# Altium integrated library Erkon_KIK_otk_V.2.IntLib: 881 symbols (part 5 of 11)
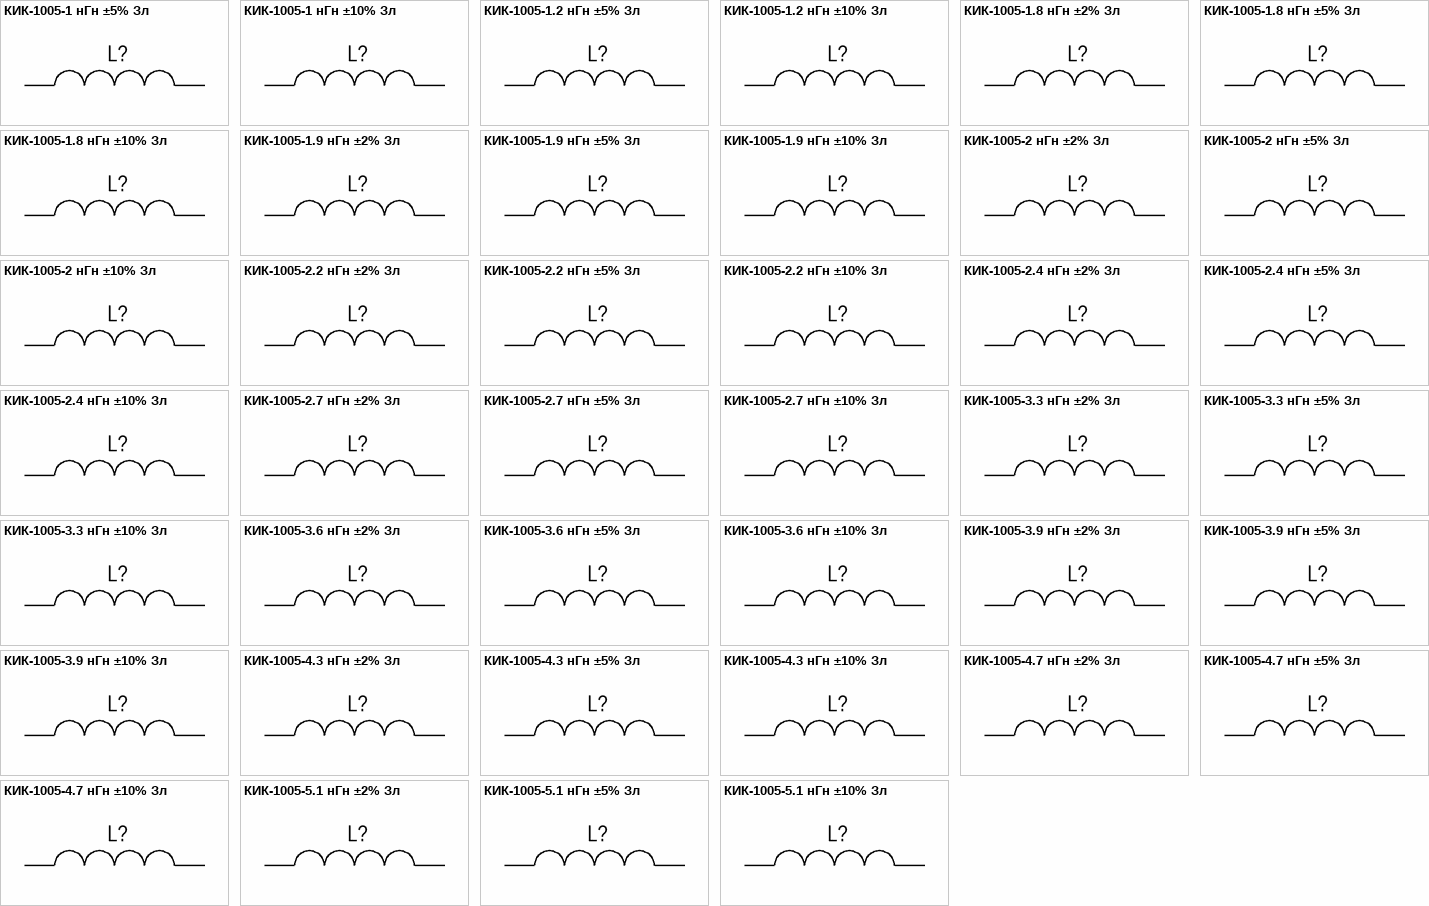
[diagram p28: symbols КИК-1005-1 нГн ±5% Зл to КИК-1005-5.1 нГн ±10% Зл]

## КИК-1005-1.9 нГн ±10% Зл
designator L?, comment 1.9 нГн ±10%  (value not drawn)
Катушка индуктивности с керамическим сердечником и золотым покрытием контактных площадок; Номиналиная индуктивность: 1.9 нГн; Добротность, не менее: 13; Резонансная частота, не менее: 11.30 ГГц; Сопротивление обмотки постоянноми току, не более: 0.090 Ом; Допустимый ток обмотки: 1040 мА; Изготовитель: АО "НПО "ЭРКОН"; Диапазон рабочих температур: от -60 до +125 ℃; Технология монтажа: SMT; Типоразмер: 1005 (0402); Упаковка: Катушка и лента
footprint КИК-1005_Зл (Катушка индуктивности с керамическим сердечником типоразмер 1005(0402))
pins: 1, 2

## КИК-1005-2 нГн ±2% Зл
designator L?, comment 2 нГн ±2%  (value not drawn)
Катушка индуктивности с керамическим сердечником и золотым покрытием контактных площадок; Номиналиная индуктивность: 2 нГн; Допускаемое отклонение индуктивности: ±5%; Добротность, не менее: 13; Резонансная частота, не менее: 11.10 ГГц; Сопротивление обмотки постоянноми току, не более: 0.090 Ом; Допустимый ток обмотки: 1040 мА; Диапазон рабочих температур: от -60 до +125 ℃; Изготовитель: АО "НПО "ЭРКОН"; Технология монтажа: SMT; Типоразмер: 1005 (0402); Упаковка: Катушка и лента
footprint КИК-1005_Зл (Катушка индуктивности с керамическим сердечником типоразмер 1005(0402))
pins: 1, 2

## КИК-1005-2 нГн ±5% Зл
designator L?, comment 2 нГн ±5%  (value not drawn)
Катушка индуктивности с керамическим сердечником и золотым покрытием контактных площадок; Номиналиная индуктивность: 2 нГн; Добротность, не менее: 13; Резонансная частота, не менее: 11.10 ГГц; Сопротивление обмотки постоянноми току, не более: 0.090 Ом; Допустимый ток обмотки: 1040 мА; Диапазон рабочих температур: от -60 до +125 ℃; Изготовитель: АО "НПО "ЭРКОН"; Технология монтажа: SMT; Типоразмер: 1005 (0402); Упаковка: Катушка и лента
footprint КИК-1005_Зл (Катушка индуктивности с керамическим сердечником типоразмер 1005(0402))
pins: 1, 2

## КИК-1005-2 нГн ±10% Зл
designator L?, comment 2 нГн ±10%  (value not drawn)
Катушка индуктивности с керамическим сердечником и золотым покрытием контактных площадок; Номиналиная индуктивность: 2 нГн; Добротность, не менее: 13; Резонансная частота, не менее: 11.10 ГГц; Сопротивление обмотки постоянноми току, не более: 0.090 Ом; Допустимый ток обмотки: 1040 мА; Изготовитель: АО "НПО "ЭРКОН"; Диапазон рабочих температур: от -60 до +125 ℃; Технология монтажа: SMT; Типоразмер: 1005 (0402); Упаковка: Катушка и лента
footprint КИК-1005_Зл (Катушка индуктивности с керамическим сердечником типоразмер 1005(0402))
pins: 1, 2

## КИК-1005-2.2 нГн ±2% Зл
designator L?, comment 2.2 нГн ±2%  (value not drawn)
Катушка индуктивности с керамическим сердечником и золотым покрытием контактных площадок; Номиналиная индуктивность: 2.2 нГн; Добротность, не менее: 18; Резонансная частота, не менее: 10.80 ГГц; Сопротивление обмотки постоянноми току, не более: 0.090 Ом; Допустимый ток обмотки: 960 мА; Изготовитель: АО "НПО "ЭРКОН"; Диапазон рабочих температур: от -60 до +125 ℃; Технология монтажа: SMT; Типоразмер: 1005 (0402); Упаковка: Катушка и лента
footprint КИК-1005_Зл (Катушка индуктивности с керамическим сердечником типоразмер 1005(0402))
pins: 1, 2

## КИК-1005-2.2 нГн ±5% Зл
designator L?, comment 2.2 нГн ±5%  (value not drawn)
Катушка индуктивности с керамическим сердечником и золотым покрытием контактных площадок; Номиналиная индуктивность: 2.2 нГн; Добротность, не менее: 18; Резонансная частота, не менее: 10.80 ГГц; Сопротивление обмотки постоянноми току, не более: 0.090 Ом; Допустимый ток обмотки: 960 мА; Изготовитель: АО "НПО "ЭРКОН"; Диапазон рабочих температур: от -60 до +125 ℃; Технология монтажа: SMT; Типоразмер: 1005 (0402); Упаковка: Катушка и лента
footprint КИК-1005_Зл (Катушка индуктивности с керамическим сердечником типоразмер 1005(0402))
pins: 1, 2

## КИК-1005-2.2 нГн ±10% Зл
designator L?, comment 2.2 нГн ±10%  (value not drawn)
Катушка индуктивности с керамическим сердечником и золотым покрытием контактных площадок; Номиналиная индуктивность: 2.2 нГн; Добротность, не менее: 18; Резонансная частота, не менее: 10.80 ГГц; Сопротивление обмотки постоянноми току, не более: 0.090 Ом; Допустимый ток обмотки: 960 мА; Диапазон рабочих температур: от -60 до +125 ℃; Технология монтажа: SMT; Типоразмер: 1005 (0402); Упаковка: Катушка и лента
footprint КИК-1005_Зл (Катушка индуктивности с керамическим сердечником типоразмер 1005(0402))
pins: 1, 2

## КИК-1005-2.4 нГн ±2% Зл
designator L?, comment 2.4нГн ±2%  (value not drawn)
Катушка индуктивности с керамическим сердечником и золотым покрытием контактных площадок; Добротность, не менее: 18; Резонансная частота, не менее: 10.50 ГГц; Сопротивление обмотки постоянноми току, не более: 0.090 Ом; Допустимый ток обмотки: 790 мА; Изготовитель: АО "НПО "ЭРКОН"; Диапазон рабочих температур: от -60 до +125 ℃; Технология монтажа: SMT; Типоразмер: 1005 (0402); Упаковка: Катушка и лента
footprint КИК-1005_Зл (Катушка индуктивности с керамическим сердечником типоразмер 1005(0402))
pins: 1, 2

## КИК-1005-2.4 нГн ±5% Зл
designator L?, comment 2.4нГн ±5%  (value not drawn)
Катушка индуктивности с керамическим сердечником и золотым покрытием контактных площадок; Добротность, не менее: 18; Резонансная частота, не менее: 10.50 ГГц; Сопротивление обмотки постоянноми току, не более: 0.090 Ом; Допустимый ток обмотки: 790 мА; Изготовитель: АО "НПО "ЭРКОН"; Диапазон рабочих температур: от -60 до +125 ℃; Технология монтажа: SMT; Типоразмер: 1005 (0402); Упаковка: Катушка и лента
footprint КИК-1005_Зл (Катушка индуктивности с керамическим сердечником типоразмер 1005(0402))
pins: 1, 2

## КИК-1005-2.4 нГн ±10% Зл
designator L?, comment 2.4нГн ±10%  (value not drawn)
Катушка индуктивности с керамическим сердечником и золотым покрытием контактных площадок; Добротность, не менее: 18; Резонансная частота, не менее: 10.50 ГГц; Сопротивление обмотки постоянноми току, не более: 0.090 Ом; Допустимый ток обмотки: 790 мА; Изготовитель: АО "НПО "ЭРКОН"; Диапазон рабочих температур: от -60 до +125 ℃; Технология монтажа: SMT; Типоразмер: 1005 (0402); Упаковка: Катушка и лента
footprint КИК-1005_Зл (Катушка индуктивности с керамическим сердечником типоразмер 1005(0402))
pins: 1, 2

## КИК-1005-2.7 нГн ±2% Зл
designator L?, comment 2.7 нГн ±2%  (value not drawn)
Катушка индуктивности с керамическим сердечником и золотым покрытием контактных площадок; Номиналиная индуктивность: 2.4 нГн; Добротность, не менее: 18; Резонансная частота, не менее: 10.40 ГГц; Сопротивление обмотки постоянноми току, не более: 0.120 Ом; Допустимый ток обмотки: 640 мА; Изготовитель: АО "НПО "ЭРКОН"; Диапазон рабочих температур: от -60 до +125 ℃; Технология монтажа: SMT; Типоразмер: 1005 (0402); Упаковка: Катушка и лента
footprint КИК-1005_Зл (Катушка индуктивности с керамическим сердечником типоразмер 1005(0402))
pins: 1, 2

## КИК-1005-2.7 нГн ±5% Зл
designator L?, comment 2.7 нГн ±5%  (value not drawn)
Катушка индуктивности с керамическим сердечником и золотым покрытием контактных площадок; Номиналиная индуктивность: 2.4 нГн; Добротность, не менее: 18; Резонансная частота, не менее: 10.40 ГГц; Сопротивление обмотки постоянноми току, не более: 0.120 Ом; Допустимый ток обмотки: 640 мА; Изготовитель: АО "НПО "ЭРКОН"; Диапазон рабочих температур: от -60 до +125 ℃; Технология монтажа: SMT; Типоразмер: 1005 (0402); Упаковка: Катушка и лента
footprint КИК-1005_Зл (Катушка индуктивности с керамическим сердечником типоразмер 1005(0402))
pins: 1, 2

## КИК-1005-2.7 нГн ±10% Зл
designator L?, comment 2.7 нГн ±10%  (value not drawn)
Катушка индуктивности с керамическим сердечником и золотым покрытием контактных площадок; Номиналиная индуктивность: 2.4 нГн; Добротность, не менее: 18; Резонансная частота, не менее: 10.40 ГГц; Сопротивление обмотки постоянноми току, не более: 0.120 Ом; Допустимый ток обмотки: 640 мА; Изготовитель: АО "НПО "ЭРКОН"; Диапазон рабочих температур: от -60 до +125 ℃; Технология монтажа: SMT; Типоразмер: 1005 (0402); Упаковка: Катушка и лента
footprint КИК-1005_Зл (Катушка индуктивности с керамическим сердечником типоразмер 1005(0402))
pins: 1, 2

## КИК-1005-3.3 нГн ±2% Зл
designator L?, comment 3.3 нГн ±2%  (value not drawn)
Катушка индуктивности с керамическим сердечником и золотым покрытием контактных площадок; Номиналиная индуктивность: 3.3нГн; Добротность, не менее: 20; Резонансная частота, не менее: 7.00 ГГц; Сопротивление обмотки постоянноми току, не более: 0.066 Ом; Допустимый ток обмотки: 840 мА; Изготовитель: АО "НПО "ЭРКОН"; Диапазон рабочих температур: от -60 до +125 ℃; Технология монтажа: SMT; Типоразмер: 1005 (0402); Упаковка: Катушка и лента
footprint КИК-1005_Зл (Катушка индуктивности с керамическим сердечником типоразмер 1005(0402))
pins: 1, 2

## КИК-1005-3.3 нГн ±5% Зл
designator L?, comment 3.3 нГн ±5%  (value not drawn)
Катушка индуктивности с керамическим сердечником и золотым покрытием контактных площадок; Номиналиная индуктивность: 3.3нГн; Добротность, не менее: 20; Резонансная частота, не менее: 7.00 ГГц; Сопротивление обмотки постоянноми току, не более: 0.066 Ом; Допустимый ток обмотки: 840 мА; Изготовитель: АО "НПО "ЭРКОН"; Диапазон рабочих температур: от -60 до +125 ℃; Технология монтажа: SMT; Типоразмер: 1005 (0402); Упаковка: Катушка и лента
footprint КИК-1005_Зл (Катушка индуктивности с керамическим сердечником типоразмер 1005(0402))
pins: 1, 2

## КИК-1005-3.3 нГн ±10% Зл
designator L?, comment 3.3 нГн ±10%  (value not drawn)
Катушка индуктивности с керамическим сердечником и золотым покрытием контактных площадок; Номиналиная индуктивность: 3.3нГн; Добротность, не менее: 20; Резонансная частота, не менее: 7.00 ГГц; Сопротивление обмотки постоянноми току, не более: 0.066 Ом; Допустимый ток обмотки: 840 мА; Изготовитель: АО "НПО "ЭРКОН"; Диапазон рабочих температур: от -60 до +125 ℃; Технология монтажа: SMT; Типоразмер: 1005 (0402); Упаковка: Катушка и лента
footprint КИК-1005_Зл (Катушка индуктивности с керамическим сердечником типоразмер 1005(0402))
pins: 1, 2

## КИК-1005-3.6 нГн ±2% Зл
designator L?, comment 3.6 нГн ±2%  (value not drawn)
Катушка индуктивности с керамическим сердечником и золотым покрытием контактных площадок; Номиналиная индуктивность: 3.6нГн; Добротность, не менее: 20; Резонансная частота, не менее: 6.80 ГГц; Сопротивление обмотки постоянноми току, не более: 0.066 Ом; Допустимый ток обмотки: 840 мА; Изготовитель: АО "НПО "ЭРКОН"; Диапазон рабочих температур: от -60 до +125 ℃; Технология монтажа: SMT; Типоразмер: 1005 (0402); Упаковка: Катушка и лента
footprint КИК-1005_Зл (Катушка индуктивности с керамическим сердечником типоразмер 1005(0402))
pins: 1, 2

## КИК-1005-3.6 нГн ±5% Зл
designator L?, comment 3.6 нГн ±5%  (value not drawn)
Катушка индуктивности с керамическим сердечником и золотым покрытием контактных площадок; Номиналиная индуктивность: 3.6нГн; Добротность, не менее: 20; Резонансная частота, не менее: 6.80 ГГц; Сопротивление обмотки постоянноми току, не более: 0.066 Ом; Допустимый ток обмотки: 840 мА; Изготовитель: АО "НПО "ЭРКОН"; Диапазон рабочих температур: от -60 до +125 ℃; Технология монтажа: SMT; Типоразмер: 1005 (0402); Упаковка: Катушка и лента
footprint КИК-1005_Зл (Катушка индуктивности с керамическим сердечником типоразмер 1005(0402))
pins: 1, 2

## КИК-1005-3.6 нГн ±10% Зл
designator L?, comment 3.6 нГн ±10%  (value not drawn)
Катушка индуктивности с керамическим сердечником и золотым покрытием контактных площадок; Номиналиная индуктивность: 3.6нГн; Допускаемое отклонение индуктивности: ±5%; Добротность, не менее: 20; Резонансная частота, не менее: 6.80 ГГц; Сопротивление обмотки постоянноми току, не более: 0.066 Ом; Допустимый ток обмотки: 840 мА; Изготовитель: АО "НПО "ЭРКОН"; Диапазон рабочих температур: от -60 до +125 ℃; Технология монтажа: SMT; Типоразмер: 1005 (0402); Упаковка: Катушка и лента
footprint КИК-1005_Зл (Катушка индуктивности с керамическим сердечником типоразмер 1005(0402))
pins: 1, 2

## КИК-1005-3.9 нГн ±2% Зл
designator L?, comment 3.9 нГн ±2%  (value not drawn)
Катушка индуктивности с керамическим сердечником и золотым покрытием контактных площадок; Номиналиная индуктивность: 3.9нГн; Добротность, не менее: 20; Резонансная частота, не менее: 6.00 ГГц; Сопротивление обмотки постоянноми току, не более: 0.066 Ом; Допустимый ток обмотки: 840 мА; Изготовитель: АО "НПО "ЭРКОН"; Диапазон рабочих температур: от -60 до +125 ℃; Технология монтажа: SMT; Типоразмер: 1005 (0402); Упаковка: Катушка и лента
footprint КИК-1005_Зл (Катушка индуктивности с керамическим сердечником типоразмер 1005(0402))
pins: 1, 2

## КИК-1005-3.9 нГн ±5% Зл
designator L?, comment 3.9 нГн ±5%  (value not drawn)
Катушка индуктивности с керамическим сердечником и золотым покрытием контактных площадок; Номиналиная индуктивность: 3.9нГн; Добротность, не менее: 20; Резонансная частота, не менее: 6.00 ГГц; Сопротивление обмотки постоянноми току, не более: 0.066 Ом; Допустимый ток обмотки: 840 мА; Изготовитель: АО "НПО "ЭРКОН"; Диапазон рабочих температур: от -60 до +125 ℃; Технология монтажа: SMT; Типоразмер: 1005 (0402); Упаковка: Катушка и лента
footprint КИК-1005_Зл (Катушка индуктивности с керамическим сердечником типоразмер 1005(0402))
pins: 1, 2

## КИК-1005-3.9 нГн ±10% Зл
designator L?, comment 3.9 нГн ±10%  (value not drawn)
Катушка индуктивности с керамическим сердечником и золотым покрытием контактных площадок; Номиналиная индуктивность: 3.9нГн; Добротность, не менее: 20; Резонансная частота, не менее: 6.00 ГГц; Сопротивление обмотки постоянноми току, не более: 0.066 Ом; Допустимый ток обмотки: 840 мА; Изготовитель: АО "НПО "ЭРКОН"; Диапазон рабочих температур: от -60 до +125 ℃; Технология монтажа: SMT; Типоразмер: 1005 (0402); Упаковка: Катушка и лента
footprint КИК-1005_Зл (Катушка индуктивности с керамическим сердечником типоразмер 1005(0402))
pins: 1, 2

## КИК-1005-4.3 нГн ±2% Зл
designator L?, comment 4.3 нГн ±2%  (value not drawn)
Катушка индуктивности с керамическим сердечником и золотым покрытием контактных площадок; Номиналиная индуктивность: 4.3 нГн; Добротность, не менее: 20; Резонансная частота, не менее: 6.00 ГГц; Сопротивление обмотки постоянноми току, не более: 0.091 Ом; Допустимый ток обмотки: 700 мА; Изготовитель: АО "НПО "ЭРКОН"; Диапазон рабочих температур: SMT; Типоразмер: 1005 (0402); Упаковка: Катушка и лента
footprint КИК-1005_Зл (Катушка индуктивности с керамическим сердечником типоразмер 1005(0402))
pins: 1, 2

## КИК-1005-4.3 нГн ±5% Зл
designator L?, comment 4.3 нГн ±5%  (value not drawn)
Катушка индуктивности с керамическим сердечником и золотым покрытием контактных площадок; Номиналиная индуктивность: 4.3 нГн; Добротность, не менее: 20; Резонансная частота, не менее: 6.00 ГГц; Сопротивление обмотки постоянноми току, не более: 0.091 Ом; Допустимый ток обмотки: 700 мА; Изготовитель: АО "НПО "ЭРКОН"; Диапазон рабочих температур: SMT; Типоразмер: 1005 (0402); Упаковка: Катушка и лента
footprint КИК-1005_Зл (Катушка индуктивности с керамическим сердечником типоразмер 1005(0402))
pins: 1, 2

## КИК-1005-4.3 нГн ±10% Зл
designator L?, comment 4.3 нГн ±10%  (value not drawn)
Катушка индуктивности с керамическим сердечником и золотым покрытием контактных площадок; Номиналиная индуктивность: 4.3нГн; Добротность, не менее: 20; Резонансная частота, не менее: 6.00 ГГц; Сопротивление обмотки постоянноми току, не более: 0.091 Ом; Допустимый ток обмотки: 700 мА; Изготовитель: АО "НПО "ЭРКОН"; Диапазон рабочих температур: от -60 до +125 ℃; Технология монтажа: SMT; Типоразмер: 1005 (0402); Упаковка: Катушка и лента
footprint КИК-1005_Зл (Катушка индуктивности с керамическим сердечником типоразмер 1005(0402))
pins: 1, 2

## КИК-1005-4.7 нГн ±2% Зл
designator L?, comment 4.7 нГн ±2%  (value not drawn)
Катушка индуктивности с керамическим сердечником и золотым покрытием контактных площадок; Номиналиная индуктивность: 4.7 нГн; Добротность, не менее: 18; Резонансная частота, не менее: 4.77 ГГц; Сопротивление обмотки постоянноми току, не более: 0.130 Ом; Допустимый ток обмотки: 640 мА; Изготовитель: АО "НПО "ЭРКОН"; Диапазон рабочих температур: от -60 до +125 ℃; Технология монтажа: SMT; Типоразмер: 1005 (0402); Упаковка: Катушка и лента
footprint КИК-1005_Зл (Катушка индуктивности с керамическим сердечником типоразмер 1005(0402))
pins: 1, 2

## КИК-1005-4.7 нГн ±5% Зл
designator L?, comment 4.7 нГн ±5%  (value not drawn)
Катушка индуктивности с керамическим сердечником и золотым покрытием контактных площадок; Номиналиная индуктивность: 4.7 нГн; Добротность, не менее: 18; Резонансная частота, не менее: 4.77 ГГц; Сопротивление обмотки постоянноми току, не более: 0.130 Ом; Допустимый ток обмотки: 640 мА; Изготовитель: АО "НПО "ЭРКОН"; Диапазон рабочих температур: от -60 до +125 ℃; Технология монтажа: SMT; Типоразмер: 1005 (0402); Упаковка: Катушка и лента
footprint КИК-1005_Зл (Катушка индуктивности с керамическим сердечником типоразмер 1005(0402))
pins: 1, 2

## КИК-1005-4.7 нГн ±10% Зл
designator L?, comment 4.7 нГн ±10%  (value not drawn)
Катушка индуктивности с керамическим сердечником и золотым покрытием контактных площадок; Номиналиная индуктивность: 4.7 нГн; Добротность, не менее: 18; Резонансная частота, не менее: 4.77 ГГц; Сопротивление обмотки постоянноми току, не более: 0.130 Ом; Допустимый ток обмотки: 640 мА; Изготовитель: АО "НПО "ЭРКОН"; Диапазон рабочих температур: от -60 до +125 ℃; Технология монтажа: SMT; Типоразмер: 1005 (0402); Упаковка: Катушка и лента
footprint КИК-1005_Зл (Катушка индуктивности с керамическим сердечником типоразмер 1005(0402))
pins: 1, 2

## КИК-1005-5.1 нГн ±2% Зл
designator L?, comment 5.1нГн ±2%  (value not drawn)
Катушка индуктивности с керамическим сердечником и золотым покрытием контактных площадок; Добротность, не менее: 20; Резонансная частота, не менее: 4.80 ГГц; Сопротивление обмотки постоянноми току, не более: 0.083 Ом; Допустимый ток обмотки: 800 мА; Изготовитель: АО "НПО "ЭРКОН"; Диапазон рабочих температур: от -60 до +125 ℃; Технология монтажа: SMT; Типоразмер: 1005 (0402); Упаковка: Катушка и лента
footprint КИК-1005_Зл (Катушка индуктивности с керамическим сердечником типоразмер 1005(0402))
pins: 1, 2

## КИК-1005-5.1 нГн ±5% Зл
designator L?, comment 5.1нГн ±5%  (value not drawn)
Катушка индуктивности с керамическим сердечником и золотым покрытием контактных площадок; Добротность, не менее: 20; Резонансная частота, не менее: 4.80 ГГц; Сопротивление обмотки постоянноми току, не более: 0.083 Ом; Допустимый ток обмотки: 800 мА; Изготовитель: АО "НПО "ЭРКОН"; Диапазон рабочих температур: от -60 до +125 ℃; Технология монтажа: SMT; Типоразмер: 1005 (0402); Упаковка: Катушка и лента
footprint КИК-1005_Зл (Катушка индуктивности с керамическим сердечником типоразмер 1005(0402))
pins: 1, 2

## КИК-1005-5.1 нГн ±10% Зл
designator L?, comment 5.1нГн ±10%  (value not drawn)
Катушка индуктивности с керамическим сердечником и золотым покрытием контактных площадок; Добротность, не менее: 20; Резонансная частота, не менее: 4.80 ГГц; Сопротивление обмотки постоянноми току, не более: 0.083 Ом; Допустимый ток обмотки: 800 мА; Изготовитель: АО "НПО "ЭРКОН"; Диапазон рабочих температур: от -60 до +125 ℃; Технология монтажа: SMT; Типоразмер: 1005 (0402); Упаковка: Катушка и лента
footprint КИК-1005_Зл (Катушка индуктивности с керамическим сердечником типоразмер 1005(0402))
pins: 1, 2

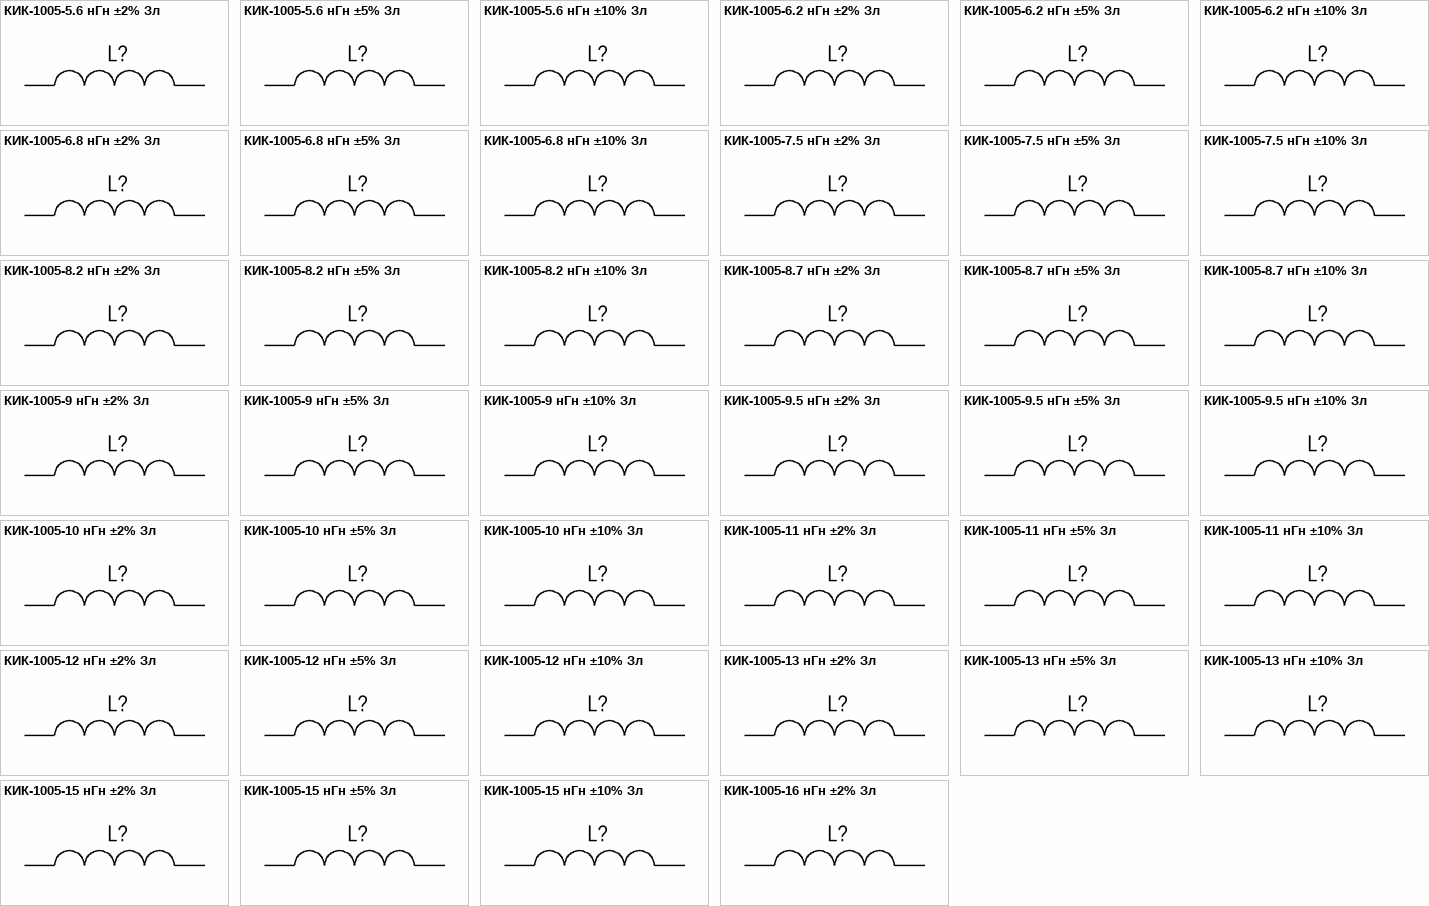
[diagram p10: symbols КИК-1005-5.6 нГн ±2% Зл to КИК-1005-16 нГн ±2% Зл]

## КИК-1005-5.6 нГн ±2% Зл
designator L?, comment 5.6нГн ±2%  (value not drawn)
Катушка индуктивности с керамическим сердечником и золотым покрытием контактных площадок; Добротность, не менее: 20; Резонансная частота, не менее: 4.80 ГГц; Сопротивление обмотки постоянноми току, не более: 0.083 Ом; Допустимый ток обмотки: 760 мА; Изготовитель: АО "НПО "ЭРКОН"; Диапазон рабочих температур: от -60 до +125 ℃; Технология монтажа: SMT; Типоразмер: 1005 (0402); Упаковка: Катушка и лента
footprint КИК-1005_Зл (Катушка индуктивности с керамическим сердечником типоразмер 1005(0402))
pins: 1, 2

## КИК-1005-5.6 нГн ±5% Зл
designator L?, comment 5.6нГн ±5%  (value not drawn)
Катушка индуктивности с керамическим сердечником и золотым покрытием контактных площадок; Добротность, не менее: 20; Резонансная частота, не менее: 4.80 ГГц; Сопротивление обмотки постоянноми току, не более: 0.083 Ом; Допустимый ток обмотки: 760 мА; Изготовитель: АО "НПО "ЭРКОН"; Диапазон рабочих температур: от -60 до +125 ℃; Технология монтажа: SMT; Типоразмер: 1005 (0402); Упаковка: Катушка и лента
footprint КИК-1005_Зл (Катушка индуктивности с керамическим сердечником типоразмер 1005(0402))
pins: 1, 2

## КИК-1005-5.6 нГн ±10% Зл
designator L?, comment 5.6 нГн ±10%  (value not drawn)
Катушка индуктивности с керамическим сердечником и золотым покрытием контактных площадок; Номиналиная индуктивность: 5.6нГн; Добротность, не менее: 20; Резонансная частота, не менее: 4.80 ГГц; Сопротивление обмотки постоянноми току, не более: 0.083 Ом; Допустимый ток обмотки: 760 мА; Изготовитель: АО "НПО "ЭРКОН"; Диапазон рабочих температур: от -60 до +125 ℃; Технология монтажа: SMT; Типоразмер: 1005 (0402); Упаковка: Катушка и лента
footprint КИК-1005_Зл (Катушка индуктивности с керамическим сердечником типоразмер 1005(0402))
pins: 1, 2

## КИК-1005-6.2 нГн ±2% Зл
designator L?, comment 6.2 нГн ±2%  (value not drawn)
Катушка индуктивности с керамическим сердечником и золотым покрытием контактных площадок; Номиналиная индуктивность: 5.6нГн; Допускаемое отклонение индуктивности: ±5%; Добротность, не менее: 20; Резонансная частота, не менее: 4.80 ГГц; Сопротивление обмотки постоянноми току, не более: 0.083 Ом; Допустимый ток обмотки: 760 мА; Изготовитель: АО "НПО "ЭРКОН"; Диапазон рабочих температур: от -60 до +125 ℃; Технология монтажа: SMT; Типоразмер: 1005 (0402); Упаковка: Катушка и лента
footprint КИК-1005_Зл (Катушка индуктивности с керамическим сердечником типоразмер 1005(0402))
pins: 1, 2

## КИК-1005-6.2 нГн ±5% Зл
designator L?, comment 6.2 нГн ±5%  (value not drawn)
Катушка индуктивности с керамическим сердечником и золотым покрытием контактных площадок; Номиналиная индуктивность: 5.6нГн; Добротность, не менее: 20; Резонансная частота, не менее: 4.80 ГГц; Сопротивление обмотки постоянноми току, не более: 0.083 Ом; Допустимый ток обмотки: 760 мА; Изготовитель: АО "НПО "ЭРКОН"; Диапазон рабочих температур: от -60 до +125 ℃; Технология монтажа: SMT; Типоразмер: 1005 (0402); Упаковка: Катушка и лента
footprint КИК-1005_Зл (Катушка индуктивности с керамическим сердечником типоразмер 1005(0402))
pins: 1, 2

## КИК-1005-6.2 нГн ±10% Зл
designator L?, comment 6.2 нГн ±10%  (value not drawn)
Катушка индуктивности с керамическим сердечником и золотым покрытием контактных площадок; Номиналиная индуктивность: 5.6нГн; Добротность, не менее: 20; Резонансная частота, не менее: 4.80 ГГц; Сопротивление обмотки постоянноми току, не более: 0.083 Ом; Допустимый ток обмотки: 760 мА; Изготовитель: АО "НПО "ЭРКОН"; Диапазон рабочих температур: от -60 до +125 ℃; Технология монтажа: SMT; Типоразмер: 1005 (0402); Упаковка: Катушка и лента
footprint КИК-1005_Зл (Катушка индуктивности с керамическим сердечником типоразмер 1005(0402))
pins: 1, 2

## КИК-1005-6.8 нГн ±2% Зл
designator L?, comment 6.8 нГн ±2%  (value not drawn)
Катушка индуктивности с керамическим сердечником и золотым покрытием контактных площадок; Номиналиная индуктивность: 5.6нГн; Допускаемое отклонение индуктивности: ±5%; Добротность, не менее: 20; Резонансная частота, не менее: 4.80 ГГц; Сопротивление обмотки постоянноми току, не более: 0.083 Ом; Допустимый ток обмотки: 680 мА; Изготовитель: АО "НПО "ЭРКОН"; Диапазон рабочих температур: от -60 до +125 ℃; Технология монтажа: SMT; Типоразмер: 1005 (0402); Упаковка: Катушка и лента
footprint КИК-1005_Зл (Катушка индуктивности с керамическим сердечником типоразмер 1005(0402))
pins: 1, 2

## КИК-1005-6.8 нГн ±5% Зл
designator L?, comment 6.8 нГн ±5%  (value not drawn)
Катушка индуктивности с керамическим сердечником и золотым покрытием контактных площадок; Номиналиная индуктивность: 5.6нГн; Добротность, не менее: 20; Резонансная частота, не менее: 4.80 ГГц; Сопротивление обмотки постоянноми току, не более: 0.083 Ом; Допустимый ток обмотки: 680 мА; Изготовитель: АО "НПО "ЭРКОН"; Диапазон рабочих температур: от -60 до +125 ℃; Технология монтажа: SMT; Типоразмер: 1005 (0402); Упаковка: Катушка и лента
footprint КИК-1005_Зл (Катушка индуктивности с керамическим сердечником типоразмер 1005(0402))
pins: 1, 2

## КИК-1005-6.8 нГн ±10% Зл
designator L?, comment 10 нГн ±5%  (value not drawn)
Катушка индуктивности с керамическим сердечником и золотым покрытием контактных площадок; Номиналиная индуктивность: 5.6нГн; Допускаемое отклонение индуктивности: ±10%; Добротность, не менее: 20; Резонансная частота, не менее: 4.80 ГГц; Сопротивление обмотки постоянноми току, не более: 0.083 Ом; Допустимый ток обмотки: 680 мА; Изготовитель: АО "НПО "ЭРКОН"; Диапазон рабочих температур: от -60 до +125 ℃; Технология монтажа: SMT; Типоразмер: 1005 (0402); Упаковка: Катушка и лента
footprint КИК-1005_Зл (Катушка индуктивности с керамическим сердечником типоразмер 1005(0402))
pins: 1, 2

## КИК-1005-7.5 нГн ±2% Зл
designator L?, comment 7.5 нГн ±2%  (value not drawn)
Катушка индуктивности с керамическим сердечником и золотым покрытием контактных площадок; Номиналиная индуктивность: 7.5нГн; Добротность, не менее: 20; Резонансная частота, не менее: 4.80 ГГц; Сопротивление обмотки постоянноми току, не более: 0.10 Ом; Допустимый ток обмотки: 680 мА; Изготовитель: АО "НПО "ЭРКОН"; Диапазон рабочих температур: от -60 до +125 ℃; Технология монтажа: SMT; Типоразмер: 1005 (0402); Упаковка: Катушка и лента
footprint КИК-1005_Зл (Катушка индуктивности с керамическим сердечником типоразмер 1005(0402))
pins: 1, 2

## КИК-1005-7.5 нГн ±5% Зл
designator L?, comment 7.5 нГн ±5%  (value not drawn)
Катушка индуктивности с керамическим сердечником и золотым покрытием контактных площадок; Номиналиная индуктивность: 7.5нГн; Добротность, не менее: 20; Резонансная частота, не менее: 4.80 ГГц; Сопротивление обмотки постоянноми току, не более: 0.10 Ом; Допустимый ток обмотки: 680 мА; Изготовитель: АО "НПО "ЭРКОН"; Диапазон рабочих температур: от -60 до +125 ℃; Технология монтажа: SMT; Типоразмер: 1005 (0402); Упаковка: Катушка и лента
footprint КИК-1005_Зл (Катушка индуктивности с керамическим сердечником типоразмер 1005(0402))
pins: 1, 2

## КИК-1005-7.5 нГн ±10% Зл
designator L?, comment 7.5 нГн ±10%  (value not drawn)
Катушка индуктивности с керамическим сердечником и золотым покрытием контактных площадок; Номиналиная индуктивность: 7.5нГн; Добротность, не менее: 20; Резонансная частота, не менее: 4.80 ГГц; Сопротивление обмотки постоянноми току, не более: 0.10 Ом; Допустимый ток обмотки: 680 мА; Изготовитель: АО "НПО "ЭРКОН"; Диапазон рабочих температур: от -60 до +125 ℃; Технология монтажа: SMT; Типоразмер: 1005 (0402); Упаковка: Катушка и лента
footprint КИК-1005_Зл (Катушка индуктивности с керамическим сердечником типоразмер 1005(0402))
pins: 1, 2

## КИК-1005-8.2 нГн ±2% Зл
designator L?, comment 8.2 нГн ±2%  (value not drawn)
Катушка индуктивности с керамическим сердечником и золотым покрытием контактных площадок; Номиналиная индуктивность: 8.2 нГн; Добротность, не менее: 20; Резонансная частота, не менее: 4.40 ГГц; Сопротивление обмотки постоянноми току, не более: 0.10 Ом; Допустимый ток обмотки: 680 мА; Изготовитель: АО "НПО "ЭРКОН"; Диапазон рабочих температур: SMT; Типоразмер: 1005 (0402); Упаковка: Катушка и лента
footprint КИК-1005_Зл (Катушка индуктивности с керамическим сердечником типоразмер 1005(0402))
pins: 1, 2

## КИК-1005-8.2 нГн ±5% Зл
designator L?, comment 8.2 нГн ±5%  (value not drawn)
Катушка индуктивности с керамическим сердечником и золотым покрытием контактных площадок; Номиналиная индуктивность: 8.2 нГн; Добротность, не менее: 20; Резонансная частота, не менее: 4.40 ГГц; Сопротивление обмотки постоянноми току, не более: 0.10 Ом; Допустимый ток обмотки: 680 мА; Изготовитель: АО "НПО "ЭРКОН"; Диапазон рабочих температур: SMT; Типоразмер: 1005 (0402); Упаковка: Катушка и лента
footprint КИК-1005_Зл (Катушка индуктивности с керамическим сердечником типоразмер 1005(0402))
pins: 1, 2

## КИК-1005-8.2 нГн ±10% Зл
designator L?, comment 8.2 нГн ±10%  (value not drawn)
Катушка индуктивности с керамическим сердечником и золотым покрытием контактных площадок; Номиналиная индуктивность: 8.2 нГн; Добротность, не менее: 20; Резонансная частота, не менее: 4.40 ГГц; Сопротивление обмотки постоянноми току, не более: 0.10 Ом; Допустимый ток обмотки: 680 мА; Изготовитель: АО "НПО "ЭРКОН"; Диапазон рабочих температур: от -60 до +125 ℃; Технология монтажа: SMT; Типоразмер: 1005 (0402); Упаковка: Катушка и лента
footprint КИК-1005_Зл (Катушка индуктивности с керамическим сердечником типоразмер 1005(0402))
pins: 1, 2

## КИК-1005-8.7 нГн ±2% Зл
designator L?, comment 8.7 нГн ±2%  (value not drawn)
Катушка индуктивности с керамическим сердечником и золотым покрытием контактных площадок; Номиналиная индуктивность: 8.7 нГн; Добротность, не менее: 20; Резонансная частота, не менее: 4.10 ГГц; Сопротивление обмотки постоянноми току, не более: 0.20 Ом; Допустимый ток обмотки: 480 мА; Изготовитель: АО "НПО "ЭРКОН"; Диапазон рабочих температур: от -60 до +125 ℃; Технология монтажа: SMT; Типоразмер: 1005 (0402); Упаковка: Катушка и лента
footprint КИК-1005_Зл (Катушка индуктивности с керамическим сердечником типоразмер 1005(0402))
pins: 1, 2

## КИК-1005-8.7 нГн ±5% Зл
designator L?, comment 8.7 нГн ±5%  (value not drawn)
Катушка индуктивности с керамическим сердечником и золотым покрытием контактных площадок; Номиналиная индуктивность: 8.7 нГн; Добротность, не менее: 20; Резонансная частота, не менее: 4.10 ГГц; Сопротивление обмотки постоянноми току, не более: 0.20 Ом; Допустимый ток обмотки: 480 мА; Изготовитель: АО "НПО "ЭРКОН"; Диапазон рабочих температур: от -60 до +125 ℃; Технология монтажа: SMT; Типоразмер: 1005 (0402); Упаковка: Катушка и лента
footprint КИК-1005_Зл (Катушка индуктивности с керамическим сердечником типоразмер 1005(0402))
pins: 1, 2

## КИК-1005-8.7 нГн ±10% Зл
designator L?, comment 8.7 нГн ±10%  (value not drawn)
Катушка индуктивности с керамическим сердечником и золотым покрытием контактных площадок; Номиналиная индуктивность: 8.7 нГн; Добротность, не менее: 20; Резонансная частота, не менее: 4.10 ГГц; Сопротивление обмотки постоянноми току, не более: 0.20 Ом; Допустимый ток обмотки: 480 мА; Изготовитель: АО "НПО "ЭРКОН"; Диапазон рабочих температур: от -60 до +125 ℃; Технология монтажа: SMT; Типоразмер: 1005 (0402); Упаковка: Катушка и лента
footprint КИК-1005_Зл (Катушка индуктивности с керамическим сердечником типоразмер 1005(0402))
pins: 1, 2

## КИК-1005-9 нГн ±2% Зл
designator L?, comment 9 нГн ±2%  (value not drawn)
Катушка индуктивности с керамическим сердечником и золотым покрытием контактных площадок; Номиналиная индуктивность: 9.0нГн; Добротность, не менее: 20; Резонансная частота, не менее: 4.16 ГГц; Сопротивление обмотки постоянноми току, не более: 0.20 Ом; Допустимый ток обмотки: 680 мА; Изготовитель: АО "НПО "ЭРКОН"; Диапазон рабочих температур: от -60 до +125 ℃; Технология монтажа: SMT; Типоразмер: 1005 (0402); Упаковка: Катушка и лента
footprint КИК-1005_Зл (Катушка индуктивности с керамическим сердечником типоразмер 1005(0402))
pins: 1, 2

## КИК-1005-9 нГн ±5% Зл
designator L?, comment 9 нГн ±5%  (value not drawn)
Катушка индуктивности с керамическим сердечником и золотым покрытием контактных площадок; Номиналиная индуктивность: 9.0нГн; Добротность, не менее: 20; Резонансная частота, не менее: 4.16 ГГц; Сопротивление обмотки постоянноми току, не более: 0.20 Ом; Допустимый ток обмотки: 680 мА; Изготовитель: АО "НПО "ЭРКОН"; Диапазон рабочих температур: от -60 до +125 ℃; Технология монтажа: SMT; Типоразмер: 1005 (0402); Упаковка: Катушка и лента
footprint КИК-1005_Зл (Катушка индуктивности с керамическим сердечником типоразмер 1005(0402))
pins: 1, 2

## КИК-1005-9 нГн ±10% Зл
designator L?, comment 9 нГн ±10%  (value not drawn)
Катушка индуктивности с керамическим сердечником и золотым покрытием контактных площадок; Номиналиная индуктивность: 9.0нГн; Добротность, не менее: 20; Резонансная частота, не менее: 4.16 ГГц; Сопротивление обмотки постоянноми току, не более: 0.20 Ом; Допустимый ток обмотки: 680 мА; Изготовитель: АО "НПО "ЭРКОН"; Диапазон рабочих температур: от -60 до +125 ℃; Технология монтажа: SMT; Типоразмер: 1005 (0402); Упаковка: Катушка и лента
footprint КИК-1005_Зл (Катушка индуктивности с керамическим сердечником типоразмер 1005(0402))
pins: 1, 2

## КИК-1005-9.5 нГн ±2% Зл
designator L?, comment 9.5 нГн ±2%  (value not drawn)
Катушка индуктивности с керамическим сердечником и золотым покрытием контактных площадок; Номиналиная индуктивность: 9.5 нГн; Добротность, не менее: 20; Резонансная частота, не менее: 4.00 ГГц; Сопротивление обмотки постоянноми току, не более: 0.20 Ом; Допустимый ток обмотки: 480 мА; Изготовитель: АО "НПО "ЭРКОН"; Диапазон рабочих температур: от -60 до +125 ℃; Технология монтажа: SMT; Типоразмер: 1005 (0402); Упаковка: Катушка и лента
footprint КИК-1005_Зл (Катушка индуктивности с керамическим сердечником типоразмер 1005(0402))
pins: 1, 2

## КИК-1005-9.5 нГн ±5% Зл
designator L?, comment 9.5 нГн ±5%  (value not drawn)
Катушка индуктивности с керамическим сердечником и золотым покрытием контактных площадок; Номиналиная индуктивность: 9.5 нГн; Добротность, не менее: 20; Резонансная частота, не менее: 4.00 ГГц; Сопротивление обмотки постоянноми току, не более: 0.20 Ом; Допустимый ток обмотки: 480 мА; Изготовитель: АО "НПО "ЭРКОН"; Диапазон рабочих температур: от -60 до +125 ℃; Технология монтажа: SMT; Типоразмер: 1005 (0402); Упаковка: Катушка и лента
footprint КИК-1005_Зл (Катушка индуктивности с керамическим сердечником типоразмер 1005(0402))
pins: 1, 2

## КИК-1005-9.5 нГн ±10% Зл
designator L?, comment 9.5 нГн ±10%  (value not drawn)
Катушка индуктивности с керамическим сердечником и золотым покрытием контактных площадок; Номиналиная индуктивность: 9.5 нГн; Добротность, не менее: 20; Резонансная частота, не менее: 4.00 ГГц; Сопротивление обмотки постоянноми току, не более: 0.20 Ом; Допустимый ток обмотки: 480 мА; Изготовитель: АО "НПО "ЭРКОН"; Диапазон рабочих температур: от -60 до +125 ℃; Технология монтажа: SMT; Типоразмер: 1005 (0402); Упаковка: Катушка и лента
footprint КИК-1005_Зл (Катушка индуктивности с керамическим сердечником типоразмер 1005(0402))
pins: 1, 2

## КИК-1005-10 нГн ±2% Зл
designator L?, comment 10 нГн ±2%  (value not drawn)
Катушка индуктивности с керамическим сердечником и золотым покрытием контактных площадок; Номиналиная индуктивность: 10 нГн; Добротность, не менее: 20; Резонансная частота, не менее: 3.90 ГГц; Сопротивление обмотки постоянноми току, не более: 0.20 Ом; Допустимый ток обмотки: 480 мА; Изготовитель: АО "НПО "ЭРКОН"; Диапазон рабочих температур: от -60 до +125 ℃; Технология монтажа: SMT; Типоразмер: 1005 (0402); Упаковка: Катушка и лента
footprint КИК-1005_Зл (Катушка индуктивности с керамическим сердечником типоразмер 1005(0402))
pins: 1, 2

## КИК-1005-10 нГн ±5% Зл
designator L?, comment 10 нГн ±5%  (value not drawn)
Катушка индуктивности с керамическим сердечником и золотым покрытием контактных площадок; Номиналиная индуктивность: 10 нГн; Добротность, не менее: 20; Резонансная частота, не менее: 3.90 ГГц; Сопротивление обмотки постоянноми току, не более: 0.20 Ом; Допустимый ток обмотки: 480 мА; Изготовитель: АО "НПО "ЭРКОН"; Диапазон рабочих температур: от -60 до +125 ℃; Технология монтажа: SMT; Типоразмер: 1005 (0402); Упаковка: Катушка и лента
footprint КИК-1005_Зл (Катушка индуктивности с керамическим сердечником типоразмер 1005(0402))
pins: 1, 2

## КИК-1005-10 нГн ±10% Зл
designator L?, comment 10 нГн ±10%  (value not drawn)
Катушка индуктивности с керамическим сердечником и золотым покрытием контактных площадок; Номиналиная индуктивность: 10 нГн; Добротность, не менее: 20; Резонансная частота, не менее: 3.90 ГГц; Сопротивление обмотки постоянноми току, не более: 0.20 Ом; Допустимый ток обмотки: 480 мА; Изготовитель: АО "НПО "ЭРКОН"; Диапазон рабочих температур: от -60 до +125 ℃; Технология монтажа: SMT; Типоразмер: 1005 (0402); Упаковка: Катушка и лента
footprint КИК-1005_Зл (Катушка индуктивности с керамическим сердечником типоразмер 1005(0402))
pins: 1, 2

## КИК-1005-11 нГн ±2% Зл
designator L?, comment 11 нГн ±2%  (value not drawn)
Катушка индуктивности с керамическим сердечником и золотым покрытием контактных площадок; Номиналиная индуктивность: 11 нГн; Добротность, не менее: 25; Резонансная частота, не менее: 3.68 ГГц; Сопротивление обмотки постоянноми току, не более: 0.12 Ом; Допустимый ток обмотки: 640 мА; Изготовитель: АО "НПО "ЭРКОН"; Диапазон рабочих температур: от -60 до +125 ℃; Технология монтажа: SMT; Типоразмер: 1005 (0402); Упаковка: Катушка и лента
footprint КИК-1005_Зл (Катушка индуктивности с керамическим сердечником типоразмер 1005(0402))
pins: 1, 2

## КИК-1005-11 нГн ±5% Зл
designator L?, comment 11 нГн ±5%  (value not drawn)
Катушка индуктивности с керамическим сердечником и золотым покрытием контактных площадок; Номиналиная индуктивность: 11 нГн; Добротность, не менее: 25; Резонансная частота, не менее: 3.68 ГГц; Сопротивление обмотки постоянноми току, не более: 0.12 Ом; Допустимый ток обмотки: 640 мА; Изготовитель: АО "НПО "ЭРКОН"; Диапазон рабочих температур: от -60 до +125 ℃; Технология монтажа: SMT; Типоразмер: 1005 (0402); Упаковка: Катушка и лента
footprint КИК-1005_Зл (Катушка индуктивности с керамическим сердечником типоразмер 1005(0402))
pins: 1, 2

## КИК-1005-11 нГн ±10% Зл
designator L?, comment 11 нГн ±10%  (value not drawn)
Катушка индуктивности с керамическим сердечником и золотым покрытием контактных площадок; Номиналиная индуктивность: 11 нГн; Добротность, не менее: 25; Резонансная частота, не менее: 3.68 ГГц; Сопротивление обмотки постоянноми току, не более: 0.12 Ом; Допустимый ток обмотки: 640 мА; Изготовитель: АО "НПО "ЭРКОН"; Диапазон рабочих температур: от -60 до +125 ℃; Технология монтажа: SMT; Типоразмер: 1005 (0402); Упаковка: Катушка и лента
footprint КИК-1005_Зл (Катушка индуктивности с керамическим сердечником типоразмер 1005(0402))
pins: 1, 2

## КИК-1005-12 нГн ±2% Зл
designator L?, comment 12 нГн ±2%  (value not drawn)
Катушка индуктивности с керамическим сердечником и золотым покрытием контактных площадок; Номиналиная индуктивность: 12 нГн; Добротность, не менее: 25; Резонансная частота, не менее: 3.60 ГГц; Сопротивление обмотки постоянноми току, не более: 0.12 Ом; Допустимый ток обмотки: 640 мА; Изготовитель: АО "НПО "ЭРКОН"; Диапазон рабочих температур: от -60 до +125 ℃; Технология монтажа: SMT; Типоразмер: 1005 (0402); Упаковка: Катушка и лента
footprint КИК-1005_Зл (Катушка индуктивности с керамическим сердечником типоразмер 1005(0402))
pins: 1, 2

## КИК-1005-12 нГн ±5% Зл
designator L?, comment 12 нГн ±5%  (value not drawn)
Катушка индуктивности с керамическим сердечником и золотым покрытием контактных площадок; Номиналиная индуктивность: 12 нГн; Добротность, не менее: 25; Резонансная частота, не менее: 3.60 ГГц; Сопротивление обмотки постоянноми току, не более: 0.12 Ом; Допустимый ток обмотки: 640 мА; Изготовитель: АО "НПО "ЭРКОН"; Диапазон рабочих температур: от -60 до +125 ℃; Технология монтажа: SMT; Типоразмер: 1005 (0402); Упаковка: Катушка и лента
footprint КИК-1005_Зл (Катушка индуктивности с керамическим сердечником типоразмер 1005(0402))
pins: 1, 2

## КИК-1005-12 нГн ±10% Зл
designator L?, comment 12 нГн ±10%  (value not drawn)
Катушка индуктивности с керамическим сердечником и золотым покрытием контактных площадок; Номиналиная индуктивность: 12 нГн; Добротность, не менее: 25; Резонансная частота, не менее: 3.60 ГГц; Сопротивление обмотки постоянноми току, не более: 0.12 Ом; Допустимый ток обмотки: 640 мА; Изготовитель: АО "НПО "ЭРКОН"; Диапазон рабочих температур: от -60 до +125 ℃; Технология монтажа: SMT; Типоразмер: 1005 (0402); Упаковка: Катушка и лента
footprint КИК-1005_Зл (Катушка индуктивности с керамическим сердечником типоразмер 1005(0402))
pins: 1, 2

## КИК-1005-13 нГн ±2% Зл
designator L?, comment 13 нГн ±2%  (value not drawn)
Катушка индуктивности с керамическим сердечником и золотым покрытием контактных площадок; Номиналиная индуктивность: 13 нГн; Добротность, не менее: 25; Резонансная частота, не менее: 3.45 ГГц; Сопротивление обмотки постоянноми току, не более: 0.21 Ом; Допустимый ток обмотки: 440 мА; Изготовитель: АО "НПО "ЭРКОН"; Диапазон рабочих температур: от -60 до +125 ℃; Технология монтажа: SMT; Типоразмер: 1005 (0402); Упаковка: Катушка и лента
footprint КИК-1005_Зл (Катушка индуктивности с керамическим сердечником типоразмер 1005(0402))
pins: 1, 2

## КИК-1005-13 нГн ±5% Зл
designator L?, comment 13 нГн ±5%  (value not drawn)
Катушка индуктивности с керамическим сердечником и золотым покрытием контактных площадок; Номиналиная индуктивность: 13 нГн; Добротность, не менее: 25; Резонансная частота, не менее: 3.45 ГГц; Сопротивление обмотки постоянноми току, не более: 0.21 Ом; Допустимый ток обмотки: 440 мА; Изготовитель: АО "НПО "ЭРКОН"; Диапазон рабочих температур: от -60 до +125 ℃; Технология монтажа: SMT; Типоразмер: 1005 (0402); Упаковка: Катушка и лента
footprint КИК-1005_Зл (Катушка индуктивности с керамическим сердечником типоразмер 1005(0402))
pins: 1, 2

## КИК-1005-13 нГн ±10% Зл
designator L?, comment 13 нГн ±10%  (value not drawn)
Катушка индуктивности с керамическим сердечником и золотым покрытием контактных площадок; Номиналиная индуктивность: 13 нГн; Добротность, не менее: 25; Резонансная частота, не менее: 3.45 ГГц; Сопротивление обмотки постоянноми току, не более: 0.21 Ом; Допустимый ток обмотки: 440 мА; Изготовитель: АО "НПО "ЭРКОН"; Диапазон рабочих температур: от -60 до +125 ℃; Технология монтажа: SMT; Типоразмер: 1005 (0402); Упаковка: Катушка и лента
footprint КИК-1005_Зл (Катушка индуктивности с керамическим сердечником типоразмер 1005(0402))
pins: 1, 2

## КИК-1005-15 нГн ±2% Зл
designator L?, comment 15 нГн ±2%  (value not drawn)
Катушка индуктивности с керамическим сердечником и золотым покрытием контактных площадок; Номиналиная индуктивность: 15 нГн; Добротность, не менее: 25; Резонансная частота, не менее: 3.28 ГГц; Сопротивление обмотки постоянноми току, не более: 0.21 Ом; Допустимый ток обмотки: 560 мА; Изготовитель: АО "НПО "ЭРКОН"; Диапазон рабочих температур: от -60 до +125 ℃; Технология монтажа: SMT; Типоразмер: 1005 (0402); Упаковка: Катушка и лента
footprint КИК-1005_Зл (Катушка индуктивности с керамическим сердечником типоразмер 1005(0402))
pins: 1, 2

## КИК-1005-15 нГн ±5% Зл
designator L?, comment 15 нГн ±5%  (value not drawn)
Катушка индуктивности с керамическим сердечником и золотым покрытием контактных площадок; Номиналиная индуктивность: 15 нГн; Добротность, не менее: 25; Резонансная частота, не менее: 3.28 ГГц; Сопротивление обмотки постоянноми току, не более: 0.21 Ом; Допустимый ток обмотки: 560 мА; Изготовитель: АО "НПО "ЭРКОН"; Диапазон рабочих температур: от -60 до +125 ℃; Технология монтажа: SMT; Типоразмер: 1005 (0402); Упаковка: Катушка и лента
footprint КИК-1005_Зл (Катушка индуктивности с керамическим сердечником типоразмер 1005(0402))
pins: 1, 2

## КИК-1005-15 нГн ±10% Зл
designator L?, comment 15 нГн ±10%  (value not drawn)
Катушка индуктивности с керамическим сердечником и золотым покрытием контактных площадок; Номиналиная индуктивность: 15 нГн; Добротность, не менее: 25; Резонансная частота, не менее: 3.28 ГГц; Сопротивление обмотки постоянноми току, не более: 0.21 Ом; Допустимый ток обмотки: 560 мА; Изготовитель: АО "НПО "ЭРКОН"; Диапазон рабочих температур: от -60 до +125 ℃; Технология монтажа: SMT; Типоразмер: 1005 (0402); Упаковка: Катушка и лента
footprint КИК-1005_Зл (Катушка индуктивности с керамическим сердечником типоразмер 1005(0402))
pins: 1, 2

## КИК-1005-16 нГн ±2% Зл
designator L?, comment 16 нГн ±2%  (value not drawn)
Катушка индуктивности с керамическим сердечником и золотым покрытием контактных площадок; Номиналиная индуктивность: 16 нГн; Добротность, не менее: 25; Резонансная частота, не менее: 3.10 ГГц; Сопротивление обмотки постоянноми току, не более: 0.22 Ом; Допустимый ток обмотки: 560 мА; Изготовитель: АО "НПО "ЭРКОН"; Диапазон рабочих температур: от -60 до +125 ℃; Технология монтажа: SMT; Типоразмер: 1005 (0402); Упаковка: Катушка и лента
footprint КИК-1005_Зл (Катушка индуктивности с керамическим сердечником типоразмер 1005(0402))
pins: 1, 2

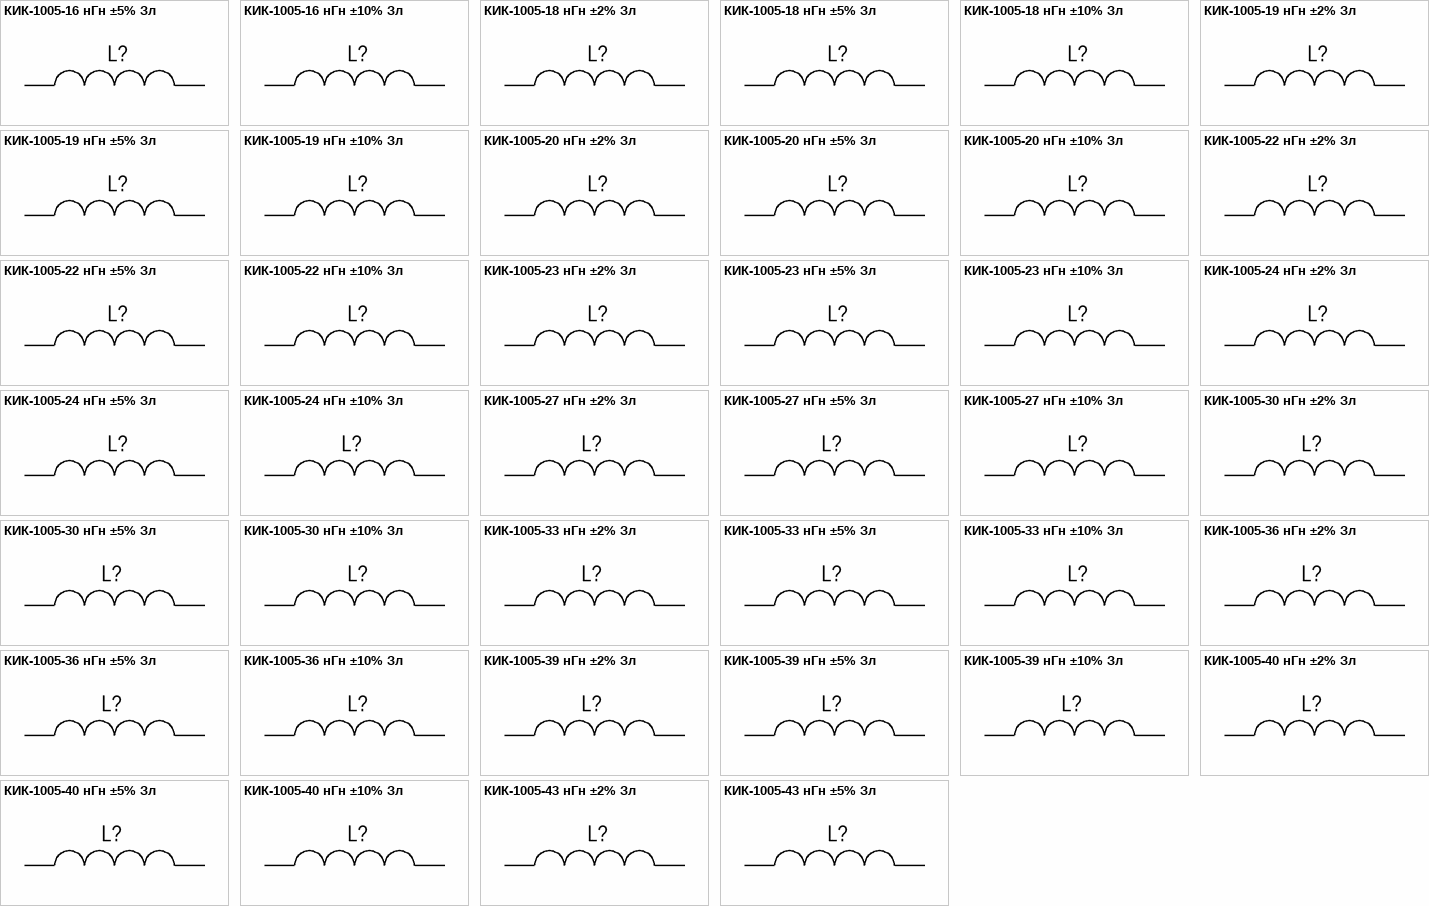
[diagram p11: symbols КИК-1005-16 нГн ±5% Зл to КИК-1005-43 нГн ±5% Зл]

## КИК-1005-16 нГн ±5% Зл
designator L?, comment 16 нГн ±5%  (value not drawn)
Катушка индуктивности с керамическим сердечником и золотым покрытием контактных площадок; Номиналиная индуктивность: 16 нГн; Добротность, не менее: 25; Резонансная частота, не менее: 3.10 ГГц; Сопротивление обмотки постоянноми току, не более: 0.22 Ом; Допустимый ток обмотки: 560 мА; Изготовитель: АО "НПО "ЭРКОН"; Диапазон рабочих температур: от -60 до +125 ℃; Технология монтажа: SMT; Типоразмер: 1005 (0402); Упаковка: Катушка и лента
footprint КИК-1005_Зл (Катушка индуктивности с керамическим сердечником типоразмер 1005(0402))
pins: 1, 2

## КИК-1005-16 нГн ±10% Зл
designator L?, comment 16 нГн ±10%  (value not drawn)
Катушка индуктивности с керамическим сердечником и золотым покрытием контактных площадок; Номиналиная индуктивность: 16 нГн; Добротность, не менее: 25; Резонансная частота, не менее: 3.10 ГГц; Сопротивление обмотки постоянноми току, не более: 0.22 Ом; Допустимый ток обмотки: 560 мА; Изготовитель: АО "НПО "ЭРКОН"; Диапазон рабочих температур: от -60 до +125 ℃; Технология монтажа: SMT; Типоразмер: 1005 (0402); Упаковка: Катушка и лента
footprint КИК-1005_Зл (Катушка индуктивности с керамическим сердечником типоразмер 1005(0402))
pins: 1, 2

## КИК-1005-18 нГн ±2% Зл
designator L?, comment 18 нГн ±2%  (value not drawn)
Катушка индуктивности с керамическим сердечником и золотым покрытием контактных площадок; Номиналиная индуктивность: 18 нГн; Добротность, не менее: 25; Резонансная частота, не менее: 3.10 ГГц; Сопротивление обмотки постоянноми току, не более: 0.23 Ом; Допустимый ток обмотки: 420 мА; Изготовитель: АО "НПО "ЭРКОН"; Диапазон рабочих температур: от -60 до +125 ℃; Технология монтажа: SMT; Типоразмер: 1005 (0402); Упаковка: Катушка и лента
footprint КИК-1005_Зл (Катушка индуктивности с керамическим сердечником типоразмер 1005(0402))
pins: 1, 2

## КИК-1005-18 нГн ±5% Зл
designator L?, comment 18 нГн ±5%  (value not drawn)
Катушка индуктивности с керамическим сердечником и золотым покрытием контактных площадок; Номиналиная индуктивность: 18 нГн; Добротность, не менее: 25; Резонансная частота, не менее: 3.10 ГГц; Сопротивление обмотки постоянноми току, не более: 0.23 Ом; Допустимый ток обмотки: 420 мА; Изготовитель: АО "НПО "ЭРКОН"; Диапазон рабочих температур: от -60 до +125 ℃; Технология монтажа: SMT; Типоразмер: 1005 (0402); Упаковка: Катушка и лента
footprint КИК-1005_Зл (Катушка индуктивности с керамическим сердечником типоразмер 1005(0402))
pins: 1, 2

## КИК-1005-18 нГн ±10% Зл
designator L?, comment 18 нГн ±10%  (value not drawn)
Катушка индуктивности с керамическим сердечником и золотым покрытием контактных площадок; Номиналиная индуктивность: 18 нГн; Добротность, не менее: 25; Резонансная частота, не менее: 3.10 ГГц; Сопротивление обмотки постоянноми току, не более: 0.23 Ом; Допустимый ток обмотки: 420 мА; Изготовитель: АО "НПО "ЭРКОН"; Диапазон рабочих температур: от -60 до +125 ℃; Технология монтажа: SMT; Типоразмер: 1005 (0402); Упаковка: Катушка и лента
footprint КИК-1005_Зл (Катушка индуктивности с керамическим сердечником типоразмер 1005(0402))
pins: 1, 2

## КИК-1005-19 нГн ±2% Зл
designator L?, comment 19 нГн ±2%  (value not drawn)
Катушка индуктивности с керамическим сердечником и золотым покрытием контактных площадок; Номиналиная индуктивность: 19 нГн; Добротность, не менее: 25; Резонансная частота, не менее: 3.04 ГГц; Сопротивление обмотки постоянноми току, не более: 0.23 Ом; Допустимый ток обмотки: 480 мА; Изготовитель: АО "НПО "ЭРКОН"; Диапазон рабочих температур: от -60 до +125 ℃; Технология монтажа: SMT; Типоразмер: 1005 (0402); Упаковка: Катушка и лента
footprint КИК-1005_Зл (Катушка индуктивности с керамическим сердечником типоразмер 1005(0402))
pins: 1, 2

## КИК-1005-19 нГн ±5% Зл
designator L?, comment 19 нГн ±5%  (value not drawn)
Катушка индуктивности с керамическим сердечником и золотым покрытием контактных площадок; Номиналиная индуктивность: 19 нГн; Добротность, не менее: 25; Резонансная частота, не менее: 3.04 ГГц; Сопротивление обмотки постоянноми току, не более: 0.23 Ом; Допустимый ток обмотки: 480 мА; Изготовитель: АО "НПО "ЭРКОН"; Диапазон рабочих температур: от -60 до +125 ℃; Технология монтажа: SMT; Типоразмер: 1005 (0402); Упаковка: Катушка и лента
footprint КИК-1005_Зл (Катушка индуктивности с керамическим сердечником типоразмер 1005(0402))
pins: 1, 2

## КИК-1005-19 нГн ±10% Зл
designator L?, comment 19 нГн ±10%  (value not drawn)
Катушка индуктивности с керамическим сердечником и золотым покрытием контактных площадок; Номиналиная индуктивность: 19 нГн; Добротность, не менее: 25; Резонансная частота, не менее: 3.04 ГГц; Сопротивление обмотки постоянноми току, не более: 0.23 Ом; Допустимый ток обмотки: 480 мА; Изготовитель: АО "НПО "ЭРКОН"; Диапазон рабочих температур: от -60 до +125 ℃; Технология монтажа: SMT; Типоразмер: 1005 (0402); Упаковка: Катушка и лента
footprint КИК-1005_Зл (Катушка индуктивности с керамическим сердечником типоразмер 1005(0402))
pins: 1, 2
